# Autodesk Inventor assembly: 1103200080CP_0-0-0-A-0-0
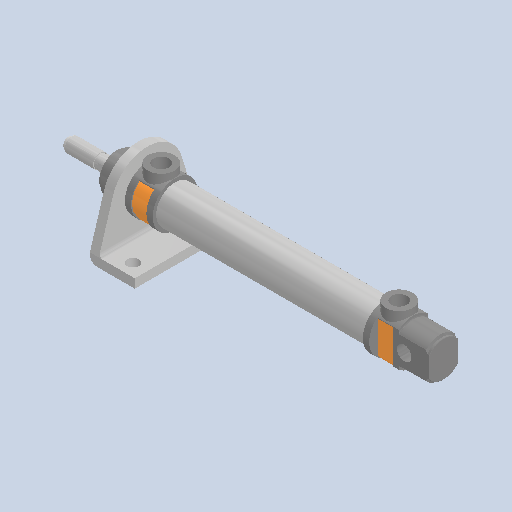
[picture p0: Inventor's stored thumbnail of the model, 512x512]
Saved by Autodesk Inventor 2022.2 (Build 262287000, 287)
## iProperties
Created: 2024-10
Part Number: 1103200080CP_0-0-0-A-0-0
Document SubType Name: Assembly
Designer: 18907419
Author: 18907419
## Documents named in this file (8)
- C:\Users\18907419\Desktop\automazione\nastro\1103200080CP_0-0-0-A-0-0.iam
- C:\Users\18907419\Desktop\automazione\nastro\ISO_6432_TP_DI20-110-HF.ipt
- C:\Users\18907419\Desktop\automazione\nastro\ISO_6432_TP_DI20-110-80-BR.ipt
- C:\Users\18907419\Desktop\automazione\nastro\ISO_6432_TP_DI20-110-HR.ipt
- C:\Users\18907419\Desktop\automazione\nastro\ISO_6432_TP_DI20-110-PR.ipt
- C:\Users\18907419\Desktop\automazione\nastro\ISO_6432_TP_DI20-11080-R.ipt
- C:\Users\18907419\Desktop\automazione\nastro\W0950200001-3_0.ipt
- C:\Users\18907419\Desktop\automazione\nastro\ISO_6432_TP_DI20-110-PF.ipt
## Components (7 placed, 7 different names)
1. ISO_6432_TP_DI20-110-HF:1
2. ISO_6432_TP_DI20-110-80-BR:1
3. ISO_6432_TP_DI20-110-HR:1
4. ISO_6432_TP_DI20-110-PR:1
5. ISO_6432_TP_DI20-11080-R:1
6. W0950200001-3_0:1
7. ISO_6432_TP_DI20-110-PF:1
